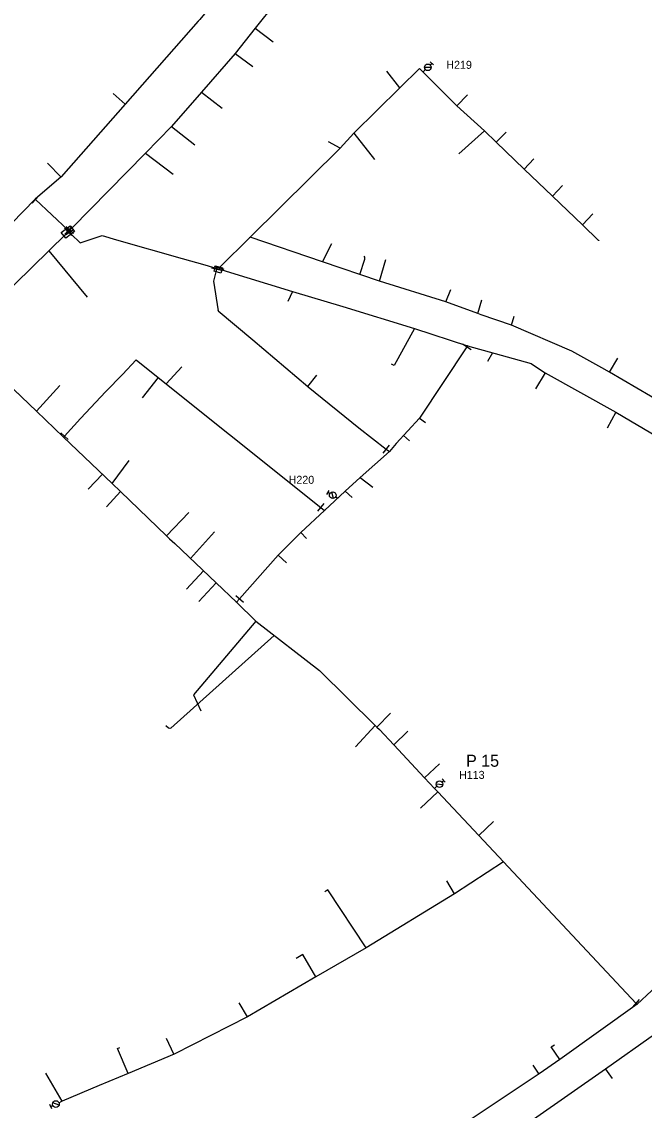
# Model space of a CAD drawing. Extents: x -548873 to -538270, y -1201997 to -1192514.
# Drawn here: x -544335.5 to -544179.8, y -1193175.5 to -1192903.4 of the extents above; entities that cross this region are included whole.
import ezdxf

# ---------------------------------------------------------------- set-up
doc = ezdxf.new("R2010")
doc.units = 0
for name, color, linetype in [('KN_HRAN_STÁTNÍ', 7, 'Continuous'), ('KN_PARC_Č', 7, 'Continuous'), ('KN_VKP_HRAN_SPORNÁ', 7, 'Continuous'), ('PK_PARC_Čv', 7, 'Continuous'), ('Vrstva 29', 7, 'Continuous')]:
    doc.layers.add(name, color=color, linetype=linetype)

# ---------------------------------------------------------------- blocks, each defined once
blk = doc.blocks.new('160')
at = {"layer": 'KN_HRAN_STÁTNÍ'}
blk.add_circle((0, 0), 0.0458, dxfattribs=at)
blk = doc.blocks.new('147')
at = {"layer": 'KN_HRAN_STÁTNÍ'}
blk.add_line((0, 1.27), (0, -1.27), dxfattribs=at)
blk = doc.blocks.new('133')
at = {"layer": 'KN_HRAN_STÁTNÍ'}
for p, q in [((0.28, 0), (0, 0)), ((0.54, 0.58), (1.7, -0.58)), ((1.94, 0), (2.52, 0)), ((2.52, 0.58), (2.52, -0.58))]:
    blk.add_line(p, q, dxfattribs=at)
blk.add_circle((1.11, 0), 0.825, dxfattribs=at)

msp = doc.modelspace()

# ---------------------------------------------------------------- linework, layer by layer
at = {"layer": 'KN_PARC_Č'}
for points in [[(-544277.138, -1192905.06), (-544272.59, -1192908.479)], [(-544282.132, -1192911.33), (-544277.7, -1192914.609)], [(-544240.973, -1192919.985), (-544244.217, -1192915.817)], [(-544309.628, -1192924.065), (-544312.583, -1192921.4)], [(-544290.552, -1192921.011), (-544285.386, -1192925.004)], [(-544226.699, -1192924.47), (-544224.072, -1192921.71)], [(-544298.023, -1192929.6), (-544292.187, -1192934.178)], [(-544252.434, -1192931.273), (-544247.254, -1192937.868)], [(-544219.794, -1192930.673), (-544226.22, -1192936.443)], [(-544216.841, -1192933.515), (-544214.367, -1192931.003)], [(-544255.871, -1192935.071), (-544258.744, -1192933.487)], [(-544304.547, -1192936.297), (-544297.62, -1192941.522)], [(-544325.647, -1192942.248), (-544329.062, -1192938.757)], [(-544209.85, -1192940.243), (-544207.469, -1192937.684)], [(-544202.789, -1192947.018), (-544200.31, -1192944.383)], [(-544195.279, -1192954.225), (-544192.716, -1192951.421)], [(-544260.263, -1192963.448), (-544257.99, -1192958.869)], [(-544328.692, -1192960.673), (-544319.141, -1192972.239)], [(-544250.967, -1192966.606), (-544249.735, -1192962.813), (-544249.722, -1192962.3), (-544249.888, -1192962.046)], [(-544246.01, -1192968.29), (-544244.44, -1192962.89)], [(-544267.767, -1192970.817), (-544268.969, -1192973.361)], [(-544229.477, -1192973.45), (-544228.18, -1192970.37)], [(-544221.483, -1192976.379), (-544220.43, -1192972.97)], [(-544213.044, -1192979.259), (-544212.36, -1192977.04)], [(-544237.271, -1192980.077), (-544242.373, -1192989.367), (-544243.045, -1192988.991)], [(-544217.759, -1192986.186), (-544219.047, -1192988.344)], [(-544188.522, -1192991.013), (-544186.485, -1192987.52)], [(-544299.38, -1192993.942), (-544295.464, -1192989.682)], [(-544204.621, -1192991.149), (-544207.019, -1192995.168)], [(-544301.333, -1192992.383), (-544305.36, -1192997.425)], [(-544263.973, -1192994.579), (-544261.724, -1192991.767)], [(-544331.778, -1193000.785), (-544325.964, -1192994.371)], [(-544186.94, -1193001.055), (-544189.077, -1193005)], [(-544236.041, -1193002.501), (-544234.547, -1193003.612)], [(-544240.008, -1193006.84), (-544238.534, -1193008.187)], [(-544312.869, -1193018.823), (-544308.609, -1193013.088)], [(-544315.312, -1193016.493), (-544318.887, -1193020.256)], [(-544250.833, -1193017.36), (-544247.713, -1193019.735)], [(-544310.788, -1193020.826), (-544314.321, -1193024.675)], [(-544254.577, -1193020.754), (-544252.866, -1193022.35)], [(-544299.266, -1193031.914), (-544293.67, -1193026.11)], [(-544293.297, -1193037.585), (-544287.241, -1193030.954)], [(-544265.681, -1193031.063), (-544264.253, -1193032.557)], [(-544271.398, -1193036.727), (-544269.287, -1193038.711)], [(-544290.063, -1193040.651), (-544294.311, -1193045.272)], [(-544286.895, -1193043.655), (-544291.206, -1193048.297)], [(-544276.925, -1193053.278), (-544292.534, -1193071.665), (-544290.727, -1193075.684)], [(-544272.381, -1193056.799), (-544298.171, -1193080.02), (-544298.447, -1193080.082), (-544298.767, -1193080.027), (-544299.449, -1193079.406)], [(-544246.667, -1193079.755), (-544243.305, -1193076.272)], [(-544247.116, -1193079.313), (-544251.999, -1193084.657)], [(-544242.485, -1193084.173), (-544238.922, -1193080.707)], [(-544234.742, -1193092.447), (-544231.069, -1193088.934)], [(-544231.471, -1193095.944), (-544235.747, -1193099.985)], [(-544221.227, -1193106.811), (-544217.493, -1193103.325)], [(-544227.297, -1193121.407), (-544229.227, -1193118.17)], [(-544249.342, -1193134.858), (-544258.967, -1193120.376), (-544259.735, -1193120.939)], [(-544261.916, -1193142.173), (-544265.198, -1193136.532), (-544266.903, -1193137.563)], [(-544279.062, -1193152.146), (-544281.089, -1193148.651)], [(-544308.834, -1193166.278), (-544311.533, -1193160.034), (-544310.914, -1193159.809)], [(-544297.468, -1193161.502), (-544299.321, -1193157.587)], [(-544200.958, -1193162.777), (-544203.098, -1193159.628), (-544202.292, -1193159.144)], [(-544206.103, -1193166.445), (-544207.603, -1193164.266)], [(-544189.492, -1193165.255), (-544187.869, -1193167.56)], [(-544325.33, -1193173.211), (-544329.435, -1193166.223)]]:
    msp.add_lwpolyline(points, dxfattribs=at)
at = {"layer": 'KN_VKP_HRAN_SPORNÁ'}
for points in [[(-544152.577, -1192768.254), (-544153.983, -1192769.772), (-544156.29, -1192772.311), (-544167.157, -1192783.67), (-544179.363, -1192796.717), (-544189.816, -1192807.891), (-544193.763, -1192812.284), (-544226.383, -1192847.804), (-544229.225, -1192850.898), (-544239.465, -1192861.842), (-544250.308, -1192873.432), (-544266.968, -1192892.289), (-544277.138, -1192905.06), (-544282.132, -1192911.33), (-544290.552, -1192921.011), (-544298.024, -1192929.601), (-544304.543, -1192936.293), (-544322.936, -1192955.028), (-544323.415, -1192955.516)], [(-544262.48, -1192869.46), (-544262.268, -1192869.673), (-544274.97, -1192884.362), (-544288.846, -1192900.409), (-544290.637, -1192902.48), (-544290.945, -1192902.835), (-544291.34, -1192903.284), (-544309.628, -1192924.065), (-544325.577, -1192942.188), (-544332.121, -1192947.8)], [(-544278.402, -1192957.285), (-544255.871, -1192935.071), (-544252.434, -1192931.273), (-544240.973, -1192919.985), (-544236.004, -1192915.092), (-544226.699, -1192924.47), (-544219.791, -1192930.676), (-544216.841, -1192933.515), (-544209.85, -1192940.243), (-544202.789, -1192947.018), (-544195.279, -1192954.225), (-544191.265, -1192958.076)], [(-544332.121, -1192947.8), (-544338.038, -1192953.851), (-544345.059, -1192961.032)], [(-544332.027, -1192947.888), (-544332.121, -1192947.8)], [(-544323.836, -1192955.556), (-544332.027, -1192947.888)], [(-544323.858, -1192955.957), (-544324.436, -1192956.521)], [(-544323.637, -1192955.742), (-544323.858, -1192955.957)], [(-544323.637, -1192955.742), (-544323.836, -1192955.556)], [(-544323.415, -1192955.516), (-544323.637, -1192955.742)], [(-544323.637, -1192955.742), (-544323.488, -1192955.964)], [(-544323.488, -1192955.964), (-544323.134, -1192956.491), (-544320.85, -1192958.67), (-544315.35, -1192956.87), (-544311.761, -1192957.9), (-544295.403, -1192962.592), (-544289.693, -1192964.231), (-544286.701, -1192965.089)], [(-544324.436, -1192956.521), (-544349.976, -1192981.433), (-544350.566, -1192982.044)], [(-544286.055, -1192965), (-544285.968, -1192964.745), (-544278.402, -1192957.285)], [(-544089.855, -1193049.347), (-544102.076, -1193042.159), (-544117.278, -1193033.217), (-544130.134, -1193025.656), (-544139.736, -1193020.008), (-544145.75, -1193016.471), (-544157.635, -1193009.145), (-544159.757, -1193007.837), (-544171.53, -1193000.951), (-544174.516, -1192999.205), (-544178.257, -1192997.017), (-544188.523, -1192991.013), (-544190.431, -1192989.897), (-544197.927, -1192985.759), (-544213.044, -1192979.259), (-544220.592, -1192976.683), (-544221.484, -1192976.379), (-544229.477, -1192973.45), (-544246.01, -1192968.29), (-544260.273, -1192963.444), (-544278.402, -1192957.285)], [(-544286.764, -1192965.325), (-544286.924, -1192965.93), (-544287.516, -1192968.243), (-544286.339, -1192975.682)], [(-544286.701, -1192965.089), (-544286.764, -1192965.325)], [(-544286.701, -1192965.089), (-544286.14, -1192965.25)], [(-544286.14, -1192965.25), (-544286.055, -1192965)], [(-544286.14, -1192965.25), (-544285.439, -1192965.451), (-544267.763, -1192970.818), (-544255.18, -1192974.639), (-544237.271, -1192980.077), (-544224.048, -1192984.419)], [(-544286.339, -1192975.682), (-544277.67, -1192982.915), (-544263.974, -1192994.578), (-544263.899, -1192994.642), (-544251.215, -1193004.934), (-544244.333, -1193010.246)], [(-544350.691, -1192982.75), (-544331.778, -1193000.785), (-544325.005, -1193007.246)], [(-544224.207, -1192984.659), (-544236.041, -1193002.501), (-544241.836, -1193008.841), (-544243.542, -1193010.857)], [(-544224.048, -1192984.419), (-544224.207, -1192984.659)], [(-544224.048, -1192984.419), (-544217.124, -1192986.365), (-544208.14, -1192988.89), (-544206.053, -1192990.229), (-544204.619, -1192991.15), (-544186.94, -1193001.055), (-544165.773, -1193013.549), (-544124.358, -1193038.476), (-544119.842, -1193041.194), (-544112.061, -1193045.877), (-544097.58, -1193054.366)], [(-544324.78, -1193007.02), (-544320.78, -1193002.63), (-544314.42, -1192995.83), (-544310.25, -1192991.56), (-544306.87, -1192987.97), (-544306.37, -1192988.36)], [(-544306.37, -1192988.36), (-544260.727, -1193024.81)], [(-544325.005, -1193007.246), (-544324.78, -1193007.02)], [(-544325.005, -1193007.246), (-544312.869, -1193018.823), (-544310.788, -1193020.826), (-544299.266, -1193031.914), (-544298.492, -1193032.659), (-544297.213, -1193033.872), (-544286.895, -1193043.655), (-544281.762, -1193048.522)], [(-544244.333, -1193010.246), (-544243.542, -1193010.857)], [(-544259.819, -1193025.621), (-544254.577, -1193020.754), (-544250.833, -1193017.36), (-544243.542, -1193010.857)], [(-544281.028, -1193047.686), (-544271.398, -1193036.727), (-544265.681, -1193031.063), (-544259.819, -1193025.621)], [(-544260.727, -1193024.81), (-544259.819, -1193025.621)], [(-544281.762, -1193048.522), (-544281.028, -1193047.686)], [(-544281.762, -1193048.522), (-544276.925, -1193053.278), (-544261.02, -1193065.602), (-544247.116, -1193079.313), (-544246.667, -1193079.755), (-544246.044, -1193080.37), (-544242.485, -1193084.173), (-544234.742, -1193092.447), (-544232.321, -1193095.035), (-544231.471, -1193095.943), (-544221.228, -1193106.81), (-544215.004, -1193113.412)], [(-544097.741, -1193054.619), (-544104.325, -1193064.926), (-544106.12, -1193067.737), (-544106.148, -1193067.781), (-544117.674, -1193083.955), (-544123.817, -1193092.575), (-544137.317, -1193107.771), (-544137.34, -1193107.797), (-544147.086, -1193116.946), (-544150.869, -1193120.455), (-544160.188, -1193129.1), (-544167.251, -1193135.652), (-544181.641, -1193149.001)], [(-544089.762, -1193059.399), (-544108.927, -1193086.404), (-544108.935, -1193086.416), (-544114.892, -1193095.313), (-544127.781, -1193110.7), (-544127.875, -1193110.813), (-544143.938, -1193126.293), (-544148.995, -1193131.167), (-544149.001, -1193131.172), (-544165.873, -1193146.274), (-544176.167, -1193155.556), (-544177.3, -1193156.577), (-544189.492, -1193165.255), (-544207.544, -1193177.774), (-544220.163, -1193186.006), (-544226.481, -1193190.224), (-544238.839, -1193198.475)], [(-544215.004, -1193113.412), (-544227.297, -1193121.407), (-544249.342, -1193134.858), (-544261.916, -1193142.173), (-544279.062, -1193152.146), (-544297.326, -1193161.442), (-544308.834, -1193166.278), (-544316.081, -1193169.324), (-544325.356, -1193173.221), (-544325.669, -1193173.353)], [(-544215.004, -1193113.412), (-544181.845, -1193148.781)], [(-544181.641, -1193149.001), (-544200.958, -1193162.777), (-544206.084, -1193166.433), (-544228.6, -1193181.349), (-544237.012, -1193186.813), (-544248.372, -1193193.969), (-544256.457, -1193198.46), (-544269.862, -1193206.002), (-544293.493, -1193218.3), (-544316.648, -1193228.974), (-544332.218, -1193233.986), (-544336.953, -1193235.523), (-544373.392, -1193247.984)], [(-544181.845, -1193148.781), (-544181.641, -1193149.001)]]:
    msp.add_lwpolyline(points, dxfattribs=at)
at = {"layer": 'PK_PARC_Čv'}
for points in [[(-544235.129, -1192915.974), (-544234.76, -1192915.61)], [(-544323.403, -1192954.424), (-544322.303, -1192955.849), (-544324.48, -1192957.53), (-544325.58, -1192956.105), (-544323.403, -1192954.424)], [(-544287.027, -1192964.447), (-544285.294, -1192964.935), (-544285.673, -1192966.282), (-544287.406, -1192965.795), (-544287.027, -1192964.447)], [(-544256.494, -1193022.534), (-544256.779, -1193022.361)], [(-544232.32, -1193095.035), (-544231.9, -1193094.69)], [(-544325.669, -1193173.353), (-544325.904, -1193173.451)]]:
    msp.add_lwpolyline(points, dxfattribs=at)

# ---------------------------------------------------------------- block references
for p, xscale, yscale, rotation in [((-544234.76, -1192915.61), 0.999999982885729, 0.9999999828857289, 45), ((-544256.779, -1193022.361), 1.0000000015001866, 1.0000000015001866, 149.00000017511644), ((-544231.9, -1193094.69), 1.0000000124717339, 1.0000000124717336, 40.00000131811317), ((-544325.904, -1193173.451), 1.0225848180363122, 1.0225848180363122, -154.18102564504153)]:
    msp.add_blockref('133', p, dxfattribs=dict(at, xscale=xscale, yscale=yscale, rotation=rotation))
at = {"layer": 'Vrstva 29'}
for name, p, xscale, yscale, rotation in [('147', (-544332.027, -1192947.888), 1.00000000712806, 1.00000000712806, 136.99999943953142), ('160', (-544332.121, -1192947.8), 1.000000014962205, 1.0000000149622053, -90.99999994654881), ('147', (-544323.858, -1192955.957), 0.999999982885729, 0.9999999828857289, -135), ('147', (-544323.836, -1192955.556), 1.00000000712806, 1.00000000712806, 136.99999943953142), ('147', (-544323.488, -1192955.964), 0.9999999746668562, 0.999999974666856, 124.00000045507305), ('147', (-544323.415, -1192955.516), 1.0000000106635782, 1.0000000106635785, -134.00000165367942), ('160', (-544323.637, -1192955.742), 1.0018265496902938, 1.0018265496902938, 173.92187301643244), ('160', (-544324.436, -1192956.521), 0.999999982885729, 0.9999999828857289, 45), ('160', (-544278.402, -1192957.285), 0.9999999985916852, 0.9999999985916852, 103.00000027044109), ('160', (-544191.265, -1192958.076), 1.00000000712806, 1.00000000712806, 136.99999943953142), ('147', (-544286.764, -1192965.325), 1.0000000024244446, 1.0000000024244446, -104.00000032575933), ('147', (-544286.055, -1192965), 1.000000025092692, 1.0000000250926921, -108.00000002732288), ('160', (-544286.701, -1192965.089), 1.0000000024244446, 1.0000000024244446, 75.99999967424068), ('160', (-544286.14, -1192965.25), 1.0365458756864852, 1.0365458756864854, 158.02850914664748), ('160', (-544286.339, -1192975.682), 0.9999999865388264, 0.9999999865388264, -59.99999955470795), ('147', (-544224.207, -1192984.659), 0.9999999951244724, 0.9999999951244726, 56.999998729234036), ('160', (-544224.048, -1192984.419), 1.0365458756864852, 1.0365458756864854, 158.02850914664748), ('160', (-544306.37, -1192988.36), 1.000000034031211, 1.0000000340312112, -38.000000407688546), ('147', (-544324.78, -1193007.02), 1.00000000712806, 1.00000000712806, 46.99999943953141), ('160', (-544325.005, -1193007.246), 1.00000000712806, 1.00000000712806, -43.0000005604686), ('147', (-544244.333, -1193010.246), 0.9999999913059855, 0.9999999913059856, 142.99999806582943), ('160', (-544243.542, -1193010.857), 1.0098116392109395, 1.0098116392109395, 10.610301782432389), ('147', (-544260.727, -1193024.81), 1.0000000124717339, 1.0000000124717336, -40.00000131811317), ('160', (-544259.819, -1193025.621), 1.00000000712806, 1.00000000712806, 43.0000005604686), ('147', (-544281.028, -1193047.686), 1.0000000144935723, 1.0000000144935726, 49.00000089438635), ('160', (-544281.762, -1193048.522), 0.9999999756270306, 0.9999999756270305, 93.00000001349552), ('160', (-544215.004, -1193113.412), 1.0000000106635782, 1.0000000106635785, 134.00000165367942), ('147', (-544181.845, -1193148.781), 1.0000000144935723, 1.0000000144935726, 139.00000089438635), ('160', (-544181.641, -1193149.001), 1.0000000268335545, 1.0000000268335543, -93.99999971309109), ('160', (-544325.669, -1193173.353), 1.0225848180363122, 1.0225848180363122, 25.81897435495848)]:
    msp.add_blockref(name, p, dxfattribs=dict(at, xscale=xscale, yscale=yscale, rotation=rotation))

# ---------------------------------------------------------------- texts
at = {"layer": 'PK_PARC_Čv'}
for s, height, p in [('H219', 2, (-544229.33, -1192915.2)), ('H220', 2, (-544268.749, -1193018.921)), ('P 15', 3, (-544224.39, -1193089.64)), ('H113', 2, (-544226.15, -1193092.67))]:
    msp.add_text(s, height=height, dxfattribs=at).set_placement(p)

doc.saveas('drawing.dxf')
